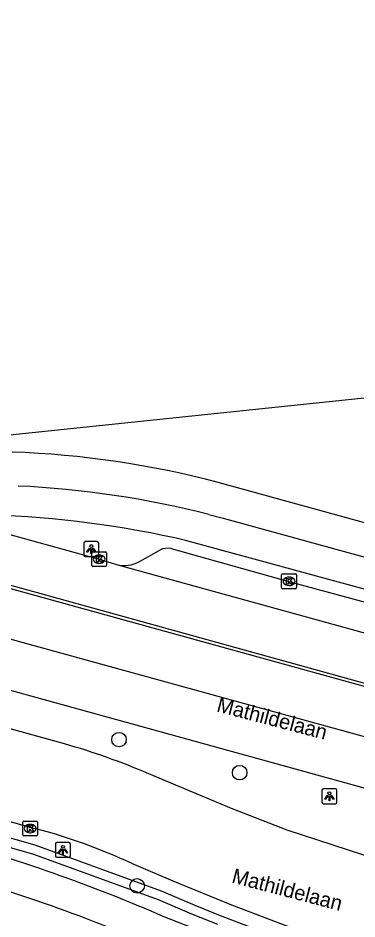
# Model space of a CAD drawing. Extents: x 160676 to 161153, y 383244 to 383713.
# Drawn here: x 160910.2 to 160932.9, y 383552.7 to 383613.3 of the extents above; entities that cross this region are included whole.
import ezdxf

# ---------------------------------------------------------------- set-up
doc = ezdxf.new("R2010")
doc.units = 0
for name, color, linetype in [('IMGEO_Boom', 7, 'Continuous'), ('IMGEO_Fietspad_gesloten', 7, 'Continuous'), ('IMGEO_Haag', 7, 'Continuous'), ('IMGEO_Kolk', 7, 'Continuous'), ('IMGEO_Lichtpunt', 7, 'Continuous'), ('IMGEO_Openbare_ruimte_label', 7, 'Continuous'), ('IMGEO_OVBaan_gesloten', 7, 'Continuous'), ('IMGEO_Pand', 7, 'Continuous'), ('IMGEO_Parkeervlak_open', 7, 'Continuous'), ('IMGEO_Rijbaan_lokaal_gesloten', 7, 'Continuous'), ('IMGEO_Voetpad_open', 7, 'Continuous')]:
    doc.layers.add(name, color=color, linetype=linetype)

msp = doc.modelspace()

# ---------------------------------------------------------------- linework, layer by layer
at = {"layer": 'IMGEO_Boom'}
for centre in [(160916.953, 383564.787), (160925.064, 383562.565), (160918.172, 383554.958)]:
    msp.add_circle(centre, 0.489, dxfattribs=at)
at = {"layer": 'IMGEO_Fietspad_gesloten'}
for points in [[(160922.998, 383579.919), (160923.962, 383579.682), (160943.827, 383574.197)], [(160942.723, 383572.366), (160921.511, 383578.159)], [(160937.384, 383546.634), (160931.005, 383548.758), (160925.725, 383550.641), (160920.031, 383552.846)]]:
    msp.add_lwpolyline(points, dxfattribs=at)
for centre, radius, start, end in [((160907.181, 383517.913), 63.992, 75.68938, 87.32596), ((160906.022, 383511.365), 68.566, 76.94433, 88.05856), ((160878.698, 383459.098), 102.456, 66.20752, 75.23218), ((160881.804, 383467.296), 91.58, 65.85393, 75.70457)]:
    msp.add_arc(centre, radius, start, end, dxfattribs=at)
at = {"layer": 'IMGEO_Haag'}
for points in [[(160927.24, 383551.612), (160923.782, 383552.939), (160922.07, 383553.628), (160919.816, 383554.602), (160911.318, 383557.69), (160877.407, 383567.315)], [(160877.247, 383566.736), (160911.134, 383557.118), (160919.594, 383554.044), (160921.832, 383553.078), (160923.562, 383552.381)]]:
    msp.add_lwpolyline(points, dxfattribs=at)
at = {"layer": 'IMGEO_Kolk'}
for p, q in [((160915.192, 383577.414), (160916.044, 383577.414)), ((160915.117, 383576.488), (160915.117, 383577.34)), ((160915.605, 383577.194), (160915.63, 383577.194)), ((160916.118, 383577.34), (160916.118, 383576.488)), ((160916.044, 383576.414), (160915.192, 383576.414)), ((160915.628, 383576.634), (160915.603, 383576.634)), ((160927.88, 383575.002), (160927.88, 383575.854)), ((160927.955, 383575.928), (160928.807, 383575.928)), ((160928.368, 383575.708), (160928.393, 383575.708)), ((160928.881, 383575.854), (160928.881, 383575.002)), ((160928.807, 383574.928), (160927.955, 383574.928)), ((160928.391, 383575.148), (160928.366, 383575.148)), ((160910.482, 383558.384), (160910.482, 383559.236)), ((160910.557, 383559.31), (160911.409, 383559.31)), ((160911.483, 383559.236), (160911.483, 383558.384)), ((160910.97, 383559.09), (160910.995, 383559.09)), ((160911.409, 383558.31), (160910.557, 383558.31)), ((160910.993, 383558.53), (160910.968, 383558.53))]:
    msp.add_line(p, q, dxfattribs=at)
for points in [[(160915.192, 383577.414), (160916.044, 383577.414)], [(160915.117, 383576.488), (160915.117, 383577.34)], [(160915.438, 383577.114), (160915.561, 383577.114), (160915.561, 383576.963), (160915.691, 383577.114), (160915.855, 383577.114), (160915.709, 383576.963), (160915.862, 383576.714), (160915.71, 383576.714), (160915.625, 383576.878), (160915.561, 383576.811), (160915.561, 383576.714), (160915.438, 383576.714), (160915.438, 383577.114)], [(160916.118, 383577.34), (160916.118, 383576.488)], [(160916.044, 383576.414), (160915.192, 383576.414)], [(160927.88, 383575.002), (160927.88, 383575.854)], [(160927.955, 383575.928), (160928.807, 383575.928)], [(160928.201, 383575.628), (160928.324, 383575.628), (160928.324, 383575.477), (160928.454, 383575.628), (160928.618, 383575.628), (160928.472, 383575.477), (160928.625, 383575.228), (160928.473, 383575.228), (160928.388, 383575.392), (160928.324, 383575.325), (160928.324, 383575.228), (160928.201, 383575.228), (160928.201, 383575.628)], [(160928.881, 383575.854), (160928.881, 383575.002)], [(160928.807, 383574.928), (160927.955, 383574.928)], [(160910.482, 383558.384), (160910.482, 383559.236)], [(160910.557, 383559.31), (160911.409, 383559.31)], [(160911.483, 383559.236), (160911.483, 383558.384)], [(160910.803, 383559.01), (160910.926, 383559.01), (160910.926, 383558.859), (160911.056, 383559.01), (160911.22, 383559.01), (160911.074, 383558.859), (160911.227, 383558.61), (160911.075, 383558.61), (160910.99, 383558.774), (160910.926, 383558.707), (160910.926, 383558.61), (160910.803, 383558.61), (160910.803, 383559.01)], [(160911.409, 383558.31), (160910.557, 383558.31)]]:
    msp.add_lwpolyline(points, dxfattribs=at)
for centre, start, end in [((160915.194, 383577.338), 91.55205, 178.44795), ((160915.194, 383577.338), 91.55205, 178.44795), ((160916.042, 383577.338), 1.55205, 88.44795), ((160916.042, 383577.338), 1.55205, 88.44795), ((160915.194, 383576.49), 181.55205, 268.44795), ((160915.194, 383576.49), 181.55205, 268.44795), ((160916.042, 383576.49), 271.55205, 358.44795), ((160916.042, 383576.49), 271.55205, 358.44795), ((160927.957, 383575.852), 91.55205, 178.44795), ((160927.957, 383575.852), 91.55205, 178.44795), ((160928.805, 383575.852), 1.55205, 88.44795), ((160928.805, 383575.852), 1.55205, 88.44795), ((160927.957, 383575.004), 181.55205, 268.44795), ((160927.957, 383575.004), 181.55205, 268.44795), ((160928.805, 383575.004), 271.55205, 358.44795), ((160928.805, 383575.004), 271.55205, 358.44795), ((160910.559, 383559.234), 91.55205, 178.44795), ((160910.559, 383559.234), 91.55205, 178.44795), ((160911.407, 383559.234), 1.55205, 88.44795), ((160911.407, 383559.234), 1.55205, 88.44795), ((160910.559, 383558.386), 181.55205, 268.44795), ((160910.559, 383558.386), 181.55205, 268.44795), ((160911.407, 383558.386), 271.55205, 358.44795), ((160911.407, 383558.386), 271.55205, 358.44795)]:
    msp.add_arc(centre, 0.0765, start, end, dxfattribs=at)
for centre, major_axis, ratio, start_param, end_param in [((160915.604, 383576.914), (-0.387, 0.002), 0.722429, 4.712389, 7.853982), ((160915.629, 383576.914), (-0.39, 0.002), 0.717154, 1.570796, 4.712389), ((160928.367, 383575.428), (-0.387, 0.002), 0.722429, 4.712389, 7.853982), ((160928.392, 383575.428), (-0.39, 0.002), 0.717154, 1.570796, 4.712389), ((160910.969, 383558.81), (-0.387, 0.002), 0.722429, 4.712389, 7.853982), ((160910.994, 383558.81), (-0.39, 0.002), 0.717154, 1.570796, 4.712389)]:
    msp.add_ellipse(centre, major_axis=major_axis, ratio=ratio, start_param=start_param, end_param=end_param, dxfattribs=at)
at = {"layer": 'IMGEO_Lichtpunt'}
for p, q in [((160914.594, 383577.999), (160914.594, 383577.192)), ((160914.594, 383577.999), (160914.594, 383577.192)), ((160915.496, 383578.094), (160914.688, 383578.094)), ((160915.496, 383578.094), (160914.688, 383578.094)), ((160915.59, 383577.192), (160915.59, 383577.999)), ((160915.59, 383577.192), (160915.59, 383577.999)), ((160914.688, 383577.098), (160915.496, 383577.098)), ((160914.688, 383577.098), (160915.496, 383577.098)), ((160930.593, 383561.38), (160930.593, 383560.573)), ((160930.593, 383561.38), (160930.593, 383560.573)), ((160931.495, 383561.475), (160930.687, 383561.475)), ((160931.495, 383561.475), (160930.687, 383561.475)), ((160931.589, 383560.573), (160931.589, 383561.38)), ((160931.589, 383560.573), (160931.589, 383561.38)), ((160930.687, 383560.479), (160931.495, 383560.479)), ((160930.687, 383560.479), (160931.495, 383560.479)), ((160912.687, 383557.781), (160912.687, 383556.974)), ((160912.687, 383557.781), (160912.687, 383556.974)), ((160913.589, 383557.876), (160912.781, 383557.876)), ((160913.589, 383557.876), (160912.781, 383557.876)), ((160913.683, 383556.974), (160913.683, 383557.781)), ((160913.683, 383556.974), (160913.683, 383557.781)), ((160912.781, 383556.88), (160913.589, 383556.88)), ((160912.781, 383556.88), (160913.589, 383556.88))]:
    msp.add_line(p, q, dxfattribs=at)
for points in [[(160914.968, 383577.663), (160915.007, 383577.635), (160914.819, 383577.373), (160914.781, 383577.4), (160914.968, 383577.663)], [(160915.07, 383577.615), (160915.117, 383577.615), (160915.117, 383577.293), (160915.07, 383577.293), (160915.07, 383577.615)], [(160915.18, 383577.635), (160915.218, 383577.662), (160915.405, 383577.4), (160915.366, 383577.372), (160915.18, 383577.635)], [(160930.967, 383561.044), (160931.006, 383561.016), (160930.818, 383560.754), (160930.78, 383560.781), (160930.967, 383561.044)], [(160931.069, 383560.996), (160931.116, 383560.996), (160931.116, 383560.674), (160931.069, 383560.674), (160931.069, 383560.996)], [(160931.179, 383561.016), (160931.217, 383561.043), (160931.404, 383560.781), (160931.365, 383560.753), (160931.179, 383561.016)], [(160913.061, 383557.445), (160913.1, 383557.417), (160912.912, 383557.155), (160912.874, 383557.182), (160913.061, 383557.445)], [(160913.163, 383557.397), (160913.21, 383557.397), (160913.21, 383557.075), (160913.163, 383557.075), (160913.163, 383557.397)], [(160913.273, 383557.417), (160913.311, 383557.444), (160913.498, 383557.182), (160913.459, 383557.154), (160913.273, 383557.417)]]:
    msp.add_lwpolyline(points, dxfattribs=at)
for centre in [(160915.093, 383577.797), (160931.092, 383561.178), (160913.186, 383557.579)]:
    msp.add_circle(centre, 0.0994, dxfattribs=at)
for centre, start, end in [((160914.688, 383577.999), 90, 180), ((160914.688, 383577.999), 90, 180), ((160915.496, 383577.999), 0, 90), ((160915.496, 383577.999), 0, 90), ((160914.688, 383577.192), 180, 270), ((160914.688, 383577.192), 180, 270), ((160915.496, 383577.192), 270, 0), ((160915.496, 383577.192), 270, 360), ((160930.687, 383561.38), 90, 180), ((160930.687, 383561.38), 90, 180), ((160931.495, 383561.38), 0, 90), ((160931.495, 383561.38), 0, 90), ((160930.687, 383560.573), 180, 270), ((160930.687, 383560.573), 180, 270), ((160931.495, 383560.573), 270, 0), ((160931.495, 383560.573), 270, 360), ((160912.781, 383557.781), 90, 180), ((160912.781, 383557.781), 90, 180), ((160913.589, 383557.781), 0, 90), ((160913.589, 383557.781), 0, 90), ((160912.781, 383556.974), 180, 270), ((160912.781, 383556.974), 180, 270), ((160913.589, 383556.974), 270, 0), ((160913.589, 383556.974), 270, 360)]:
    msp.add_arc(centre, 0.0946, start, end, dxfattribs=at)
at = {"layer": 'IMGEO_OVBaan_gesloten'}
for points in [[(160977.148, 383558.794), (160975.387, 383558.61), (160968.725, 383558.524), (160962.841, 383558.697), (160956.785, 383559.216), (160950.815, 383560.255), (160942.076, 383562.592), (160890.249, 383576.873), (160774.938, 383608.123), (160770.415, 383609.332), (160766.781, 383610.37), (160761.763, 383612.059), (160756.884, 383613.99)], [(160797.835, 383598.49), (160870.684, 383578.867), (160946.568, 383557.927)], [(160949.177, 383564.05), (160942.127, 383565.955), (160880.388, 383583.018)]]:
    msp.add_lwpolyline(points, dxfattribs=at)
at = {"layer": 'IMGEO_Pand'}
msp.add_lwpolyline([(160905.51, 383584.853), (160940.741, 383588.532), (160941.315, 383583.041), (160941.844, 383582.612), (160954.067, 383583.889)], dxfattribs=at)
at = {"layer": 'IMGEO_Parkeervlak_open'}
for points in [[(160918.327, 383576.756), (160919.688, 383577.526)], [(160920.462, 383577.626), (160928.377, 383575.427), (160942.374, 383571.622)]]:
    msp.add_lwpolyline(points, dxfattribs=at)
for centre, radius, start, end in [((160920.215, 383576.493), 1.16, 77.70508, 117.01847), ((160917.31, 383578.57), 2.079, 255.59059, 299.26583)]:
    msp.add_arc(centre, radius, start, end, dxfattribs=at)
at = {"layer": 'IMGEO_Rijbaan_lokaal_gesloten'}
for points in [[(160913.282, 383564.496), (160869.874, 383576.512), (160797.171, 383596.125)], [(160880.388, 383583.018), (160880.432, 383583.23), (160883.368, 383582.463), (160942.181, 383566.161)], [(160900.478, 383581.054), (160900.672, 383581.034), (160915.614, 383576.913), (160916.793, 383576.556)], [(160916.793, 383576.556), (160941.567, 383569.725)], [(160877.64, 383568.157), (160899.725, 383562.047), (160911.387, 383558.791)], [(160936.421, 383556.028), (160928.246, 383558.692), (160924.508, 383560.159), (160918.949, 383562.487)], [(160917.783, 383556.475), (160920.566, 383555.292), (160924.508, 383553.676), (160927.984, 383552.348), (160930.113, 383551.585), (160932.828, 383550.717), (160936.687, 383549.561), (160940.695, 383548.433), (160944.738, 383547.376), (160947.811, 383546.648), (160950.907, 383545.998), (160954.757, 383545.293), (160958.901, 383544.607), (160962.174, 383544.134), (160963.712, 383543.929)]]:
    msp.add_lwpolyline(points, dxfattribs=at)
for centre, radius, start, end in [((160901.399, 383521.98), 44.146, 66.57534, 74.38495), ((160901.669, 383521.963), 38.088, 64.9714, 75.21782)]:
    msp.add_arc(centre, radius, start, end, dxfattribs=at)
at = {"layer": 'IMGEO_Voetpad_open'}
msp.add_lwpolyline([(160953.077, 383578.527), (160950.172, 383578.233), (160950.193, 383578.027), (160947.052, 383577.699), (160947.02, 383577.997), (160944.303, 383577.711), (160944.295, 383577.422), (160943.007, 383577.314), (160943.059, 383576.719), (160923.625, 383582.077)], dxfattribs=at)
msp.add_arc((160907.489, 383520.569), 63.589, 75.30049, 87.93557, dxfattribs=at)

# ---------------------------------------------------------------- texts
at = {"layer": 'IMGEO_Openbare_ruimte_label'}
for p in [(160923.453, 383566.692), (160924.471, 383555.186)]:
    msp.add_text('Mathildelaan', height=1, rotation=345.33813, dxfattribs=at).set_placement(p)

doc.saveas('drawing.dxf')
